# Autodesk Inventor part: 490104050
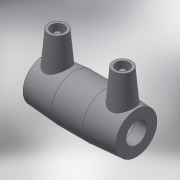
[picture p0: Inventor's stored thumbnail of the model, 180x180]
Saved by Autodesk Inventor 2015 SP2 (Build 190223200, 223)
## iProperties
Created: 2017-06
Part Number: 490104050
Material: Generic
Description: PLASSON COUPLER 50-50
Document SubType Name: Modeling
Designer: KIM
Mass: 55.0731 g
Surface Area: 148.067 cm^2
Volume: 55.0731 cm^3
Density: 1 g/cm^3
Appearance: Default
Author: KIM
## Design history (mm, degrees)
derived "490104.ipt"
feature "Solid1::490104.ipt"
tag "TaggingFeature1"
body "Solid1"
other parameters: "d0" = 101, "d2" = 67, "d3" = 49, "d4" = 33.66667, "d5" = 60.3, "d6" = 47.5, "d8" = 168 deg, "d10" = 19.6, "d11" = 6.53333, "d13" = 101, "d14" = 17.6296, "d15" = 49, "d16" = 49, "d17" = 47.5, "d19" = 3.52592, "d20" = 168 deg, "d22" = 62.98, "d23" = 67, "d24" = 61.0906, "d25" = 135 deg, "d26" = 40.4, "d27" = 135 deg, "d29" = 51, "d30" = 14, "d31" = 35.35, "d34" = 5 deg, "d35" = 15, "d39" = 5 deg, "d41" = 4, "d42" = 14, "d43" = 0, "d45" = 4, "d46" = 14, "d47" = 0, "d48" = 3, "d49" = 0, "d50" = 3, "d51" = 0, "d52" = 14.21, "d53" = 3.5525, "L_" = 101, "L_1" = 49, "D_" = 67, "A_" = 51, "d_2" = 12
